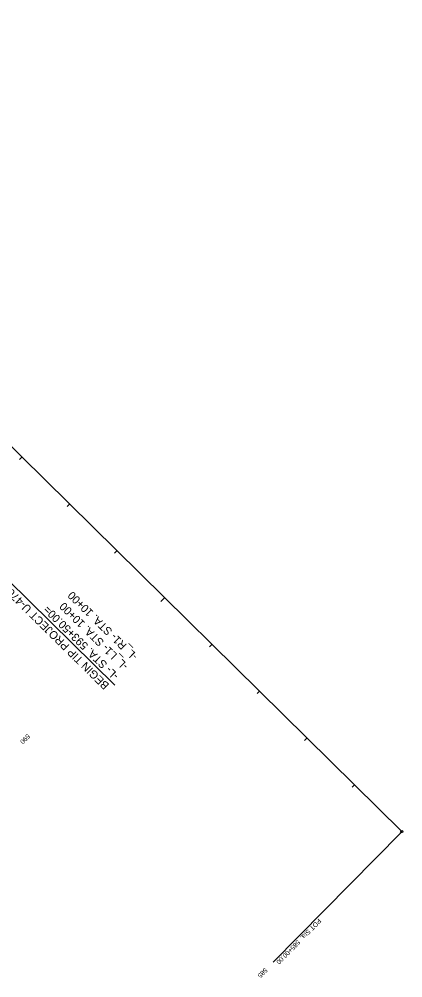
# Model space of a CAD drawing. Extents: x 1262642 to 1268358, y 767825 to 773481.
# Drawn here: x 1267782 to 1268358, y 770391 to 771829 of the extents above; entities that cross this region are included whole.
import ezdxf

# ---------------------------------------------------------------- set-up
doc = ezdxf.new("R2010")
doc.units = 0
for name, color, linetype in [('Prop Horizontal Alignment', 7, 'Continuous'), ('Prop Horizontal Alignment Station Label', 7, 'Continuous'), ('Prop Horizontal Alignment Tick Label', 7, 'Continuous'), ('Prop Horizontal Alignment Tick Large', 7, 'Continuous'), ('Prop Horizontal Alignment Tick Small', 7, 'Continuous')]:
    doc.layers.add(name, color=color, linetype=linetype)

msp = doc.modelspace()

# ---------------------------------------------------------------- linework, layer by layer
at = {"layer": 'Prop Horizontal Alignment'}
msp.add_line((1268356.2, 770610), (1267043.4, 771903.5), dxfattribs=at)
at = {"layer": 'Prop Horizontal Alignment Station Label'}
msp.add_line((1268355.1, 770608.9), (1268163.2, 770414.1), dxfattribs=at)
msp.add_lwpolyline([(1267732.7, 771019.4), (1267925.4, 770829.7)], dxfattribs=at)
msp.add_circle((1268356.2, 770610), 1.5, dxfattribs=at)
at = {"layer": 'Prop Horizontal Alignment Tick Large'}
for p, q in [((1268000, 770960.9), (1267994.4, 770955.2)), ((1268356.2, 770610), (1268350.6, 770604.3))]:
    msp.add_line(p, q, dxfattribs=at)
at = {"layer": 'Prop Horizontal Alignment Tick Small'}
for p, q in [((1267786.3, 771171.5), (1267782.8, 771167.9)), ((1267857.6, 771101.3), (1267854.1, 771097.7)), ((1267928.8, 771031.1), (1267925.3, 771027.5)), ((1268071.3, 770890.7), (1268067.8, 770887.2)), ((1268142.5, 770820.5), (1268139, 770817)), ((1268213.7, 770750.4), (1268210.2, 770746.8)), ((1268285, 770680.2), (1268281.5, 770676.6))]:
    msp.add_line(p, q, dxfattribs=at)

# ---------------------------------------------------------------- texts
at = {"layer": 'Prop Horizontal Alignment Station Label'}
for s, height, rotation, p in [('BEGIN TIP PROJECT U-4700CB', 12, 135.4239, (1267918, 770830.4)), ('-L_R1- STA. 10+00', 12, 135.4239, (1267960.9, 770874)), ('-L_L1- STA. 10+00 ', 12, 135.4239, (1267946.6, 770859.4)), ('-L- STA. 593+50.00=', 12, 135.4239, (1267932.3, 770844.9)), ('POT Sta.  585+00.00', 7, 225.4239, (1268231.1, 770480.1))]:
    msp.add_text(s, height=height, rotation=rotation, dxfattribs=at).set_placement(p)
at = {"layer": 'Prop Horizontal Alignment Tick Label'}
for s, p in [('590', (1267794.2, 770757)), ('585', (1268150.5, 770406.2))]:
    msp.add_text(s, height=7, rotation=225.4239, dxfattribs=at).set_placement(p)

doc.saveas('drawing.dxf')
